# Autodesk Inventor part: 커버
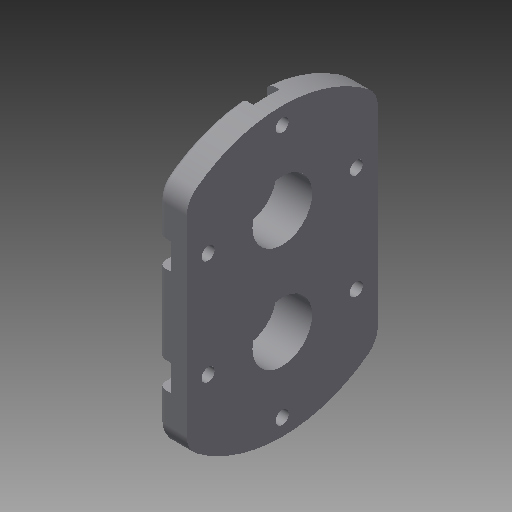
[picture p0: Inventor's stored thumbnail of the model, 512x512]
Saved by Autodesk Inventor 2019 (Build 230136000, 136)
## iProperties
Created: 2019-03
Part Number: 커버
Material: 알루미늄 6061
Document SubType Name: Modeling
Designer: mduedu
Density: 1 g/cm^3
Appearance: 기본값
Author: mduedu
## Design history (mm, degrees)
sketch "스케치1"
  geometry: L1 (44.721, -40)-(-44.721, -40); L2 (44.721, 40)-(-44.721, 40); A1 r 60 centre (0, 0) between (44.721, -40) and (44.721, 40); A2 r 60 centre (0, 0) between (-44.721, 40) and (-44.721, -40); 5 further points
  constraints: 6 point on circle, 4 end point, 2 centre point, 2 coincident, 2 horizontal alignment, 2 midpoint, 2 vertical alignment, 1 horizontal, 1 parallel
  dimensions: "d0" = 60 radius of A1; "d2" = 80 distance between parallel lines of L2 L1; "d3" = 120 distance of point (-60, 0) point (60, 0) (derived)
extrude "돌출1" new body sketch "스케치1" distance "d4" = 12; taper "d5" = 0 deg
sketch "스케치2"
  geometry: L1 (-20, -22)-(20, -22); L2 (20, -22)-(20, 22); L3 (20, 22)-(-20, 22); L4 (-20, 22)-(-20, -22); L5 (-20, -22)-(20, 22); L6 (20, -22)-(-20, 22); 3 further points
  constraints: 12 end point, 4 midpoint, 2 horizontal alignment, 2 parallel, 1 horizontal, 1 perpendicular, 4 other
  dimensions: "d6" = 40 distance between parallel lines of L2 L4; "d8" = 44 distance between parallel lines of L1 L3
extrude "돌출2" join sketch "스케치2" distance "d9" = 10; taper "d10" = 0 deg
fillet "모깎기1" dims "d11" = 10
fillet "모깎기2" dims "d12" = 3
sketch "스케치3"
  geometry: L1 (31, -22)-(31, 22); L2 (-31, 22)-(-31, -22); L3 (-31, -22)-(31, 22); L4 (31, -22)-(-31, 22); A1 r 31 centre (0, 22) between (31, 22) and (-31, 22); A2 r 31 centre (0, -22) between (-31, -22) and (31, -22); 7 further points
  constraints: 8 end point, 6 point on circle, 4 coincident, 3 tangent, 2 centre point, 2 midpoint, 1 parallel, 1 vertical, 1 vertical alignment
  dimensions: "d13" = 31 radius of A1; "d15" = 44 distance of A2.centre A1.centre
hole "구멍2" sketch "스케치3" at (-31, 22), (-31, -22), (31, -22), (31, 22), (0, 53), (0, -53) diameter "d28" = 5.5; stored, may be unused: countersink angle "d32" = 90 deg, drill point angle "d34" = 118 deg; dims "d29" = 6, "d30" = 4, "d31" = 2, "d33" = 8
sketch "스케치5"
  geometry: L1 (-40, 40)-(-40, -40) reference; L2 (40, -40)-(40, 40) reference; L3 (-5.5, 53)-(-5.5, 59.747); L4 (5.5, 53)-(5.5, 59.747); L5 (-31, 27.5)-(-40, 27.5); L6 (-31, 16.5)-(-40, 16.5); L7 (-31, -16.5)-(-40, -16.5); L8 (-31, -27.5)-(-40, -27.5); L9 (-5.5, -53)-(-5.5, -59.747); L10 (5.5, -53)-(5.5, -59.747); L11 (31, -27.5)-(40, -27.5); L12 (31, -16.5)-(40, -16.5); L13 (31, 16.5)-(40, 16.5); L14 (31, 27.5)-(40, 27.5); C1 r 2.75 at (0, 53) reference; C2 r 2.75 at (-31, 22) reference; C3 r 2.75 at (-31, -22) reference; C4 r 2.75 at (0, -53) reference; C5 r 2.75 at (31, -22) reference; C6 r 2.75 at (31, 22) reference; A1 r 60 centre (0, 0) between (36, 48) and (-36, 48) reference; A2 r 10 centre (-30, 40) between (-36, 48) and (-40, 40) reference; A3 r 10 centre (-30, -40) between (-40, -40) and (-36, -48) reference; A4 r 60 centre (0, 0) between (-36, -48) and (36, -48) reference; A5 r 10 centre (30, -40) between (36, -48) and (40, -40) reference; A6 r 10 centre (30, 40) between (40, 40) and (36, 48) reference; A7 r 5.5 centre (0, 53) between (-5.5, 53) and (5.5, 53); A8 r 5.5 centre (-31, 22) between (-31, 16.5) and (-31, 27.5); A9 r 5.5 centre (-31, -22) between (-31, -27.5) and (-31, -16.5); A10 r 5.5 centre (0, -53) between (5.5, -53) and (-5.5, -53); A11 r 5.5 centre (31, -22) between (31, -16.5) and (31, -27.5); A12 r 5.5 centre (31, 22) between (31, 27.5) and (31, 16.5); 1 further point
  constraints: 24 end point, 16 point on circle, 12 tangent, 8 parallel, 8 point on line, 6 centre point, 5 concentric, 4 horizontal, 1 coincident, 1 vertical
  dimensions: "d35" = 11 diameter of A7; "d36" = 11 diameter of A8; "d37" = 11 diameter of A9; "d38" = 11 diameter of A10; "d39" = 11 diameter of A11; "d40" = 11 diameter of A12
extrude "돌출4" cut sketch "스케치5" distance "d41" = 5.4; taper "d42" = 0 deg
sketch "스케치6"
  geometry: C1 r 12.5 at (0, 22); 1 further point
  constraints: 1 centre point, 1 vertical alignment
  dimensions: "d43" = 25 diameter of C1; "d45" = 22 distance of C1.centre point (0, 0)
extrude "돌출5" cut sketch "스케치6" distance "d47" = 15; taper "d48" = 0 deg
node "솔리드1"
mirror "대칭1"
